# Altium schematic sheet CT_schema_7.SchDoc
size 278 x 170 mm
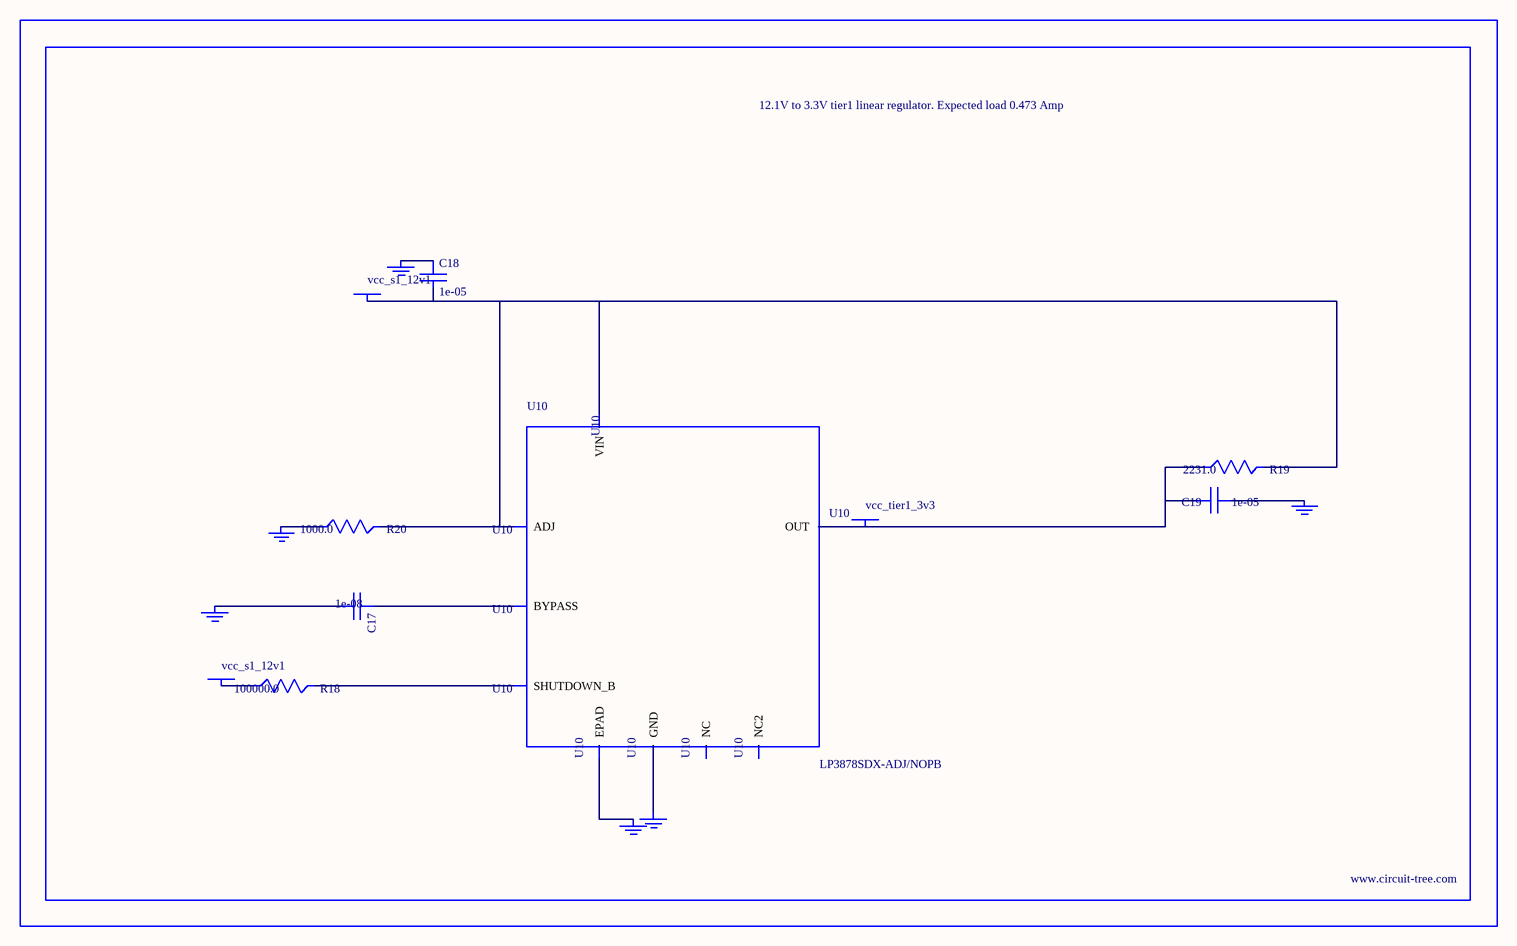
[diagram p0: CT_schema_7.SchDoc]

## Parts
BORDER6  (no value)
C17  1e-08  [C0402]
C18  1e-05  [C1210]
C19  1e-05  [C1210]
GND_INSTANCE_6_0  (no value)
GND_INSTANCE_6_1  (no value)
GND_INSTANCE_6_2  (no value)
GND_INSTANCE_6_3  (no value)
GND_INSTANCE_6_4  (no value)
GND_INSTANCE_6_5  (no value)
POWER_INSTANCE_6_0  vcc_s1_12v1
POWER_INSTANCE_6_1  vcc_s1_12v1
POWER_INSTANCE_6_2  vcc_tier1_3v3
R18  100000.0  [R0603]
R19  2231.0  [R0603]
R20  1000.0  [R0603]
U10  LP3878SDX-ADJ/NOPB  [WSON-8]

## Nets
NetC17_1: C17.1 U10.1(BYPASS)
NetC17_2: C17.2 GND_INSTANCE_6_0.0(GND)
NetC18_1: C18.1 GND_INSTANCE_6_1.0(GND)
NetC18_2: C18.2 POWER_INSTANCE_6_0.0(PWR) R19.2 R20.2 U10.4(VIN) U10.6(ADJ)
NetC19_1: C19.1 GND_INSTANCE_6_2.0(GND)
NetC19_2: C19.2 POWER_INSTANCE_6_2.0(PWR) R19.1 U10.5(OUT)
NetGND_INSTANCE_6_3_0: GND_INSTANCE_6_3.0(GND) R20.1
NetGND_INSTANCE_6_4_0: GND_INSTANCE_6_4.0(GND) U10.PAD(EPAD)
NetGND_INSTANCE_6_5_0: GND_INSTANCE_6_5.0(GND) U10.3(GND)
NetPOWER_INSTANCE_6_1_0: POWER_INSTANCE_6_1.0(PWR) R18.1
NetR18_2: R18.2 U10.8(SHUTDOWN_B)

Not connected (* = marked no-connect by the designer): U10 2(NC) 7(NC2)

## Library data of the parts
BORDER6 = BORDER_PAGE6
C17 = C0402C103K3RAC
C18 = C1210C106K5PACTU
C19 = GRM32DR61E106MA12L
GND_INSTANCE_6_0-GND_INSTANCE_6_5 = GND
POWER_INSTANCE_6_0-POWER_INSTANCE_6_2 = PWR
R18 = RC0603JR-07100KL
R19 = R19
R20 = RC0603JR-071KL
